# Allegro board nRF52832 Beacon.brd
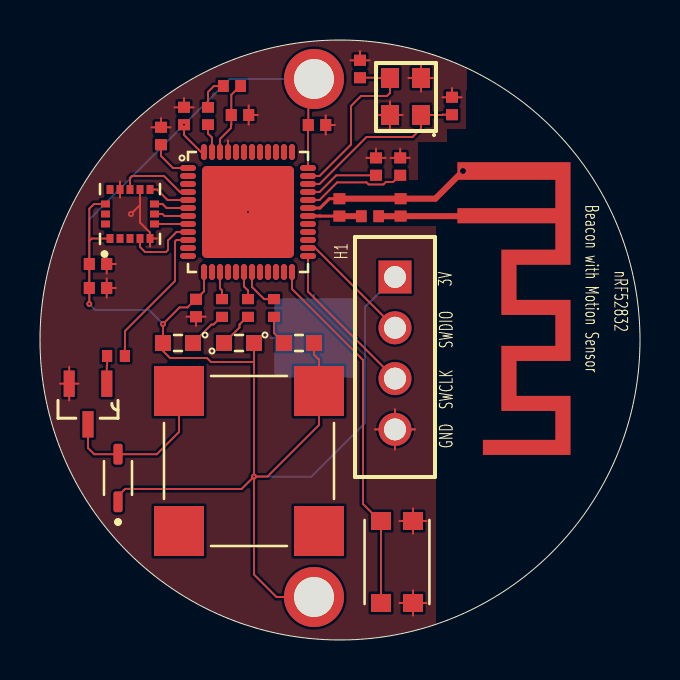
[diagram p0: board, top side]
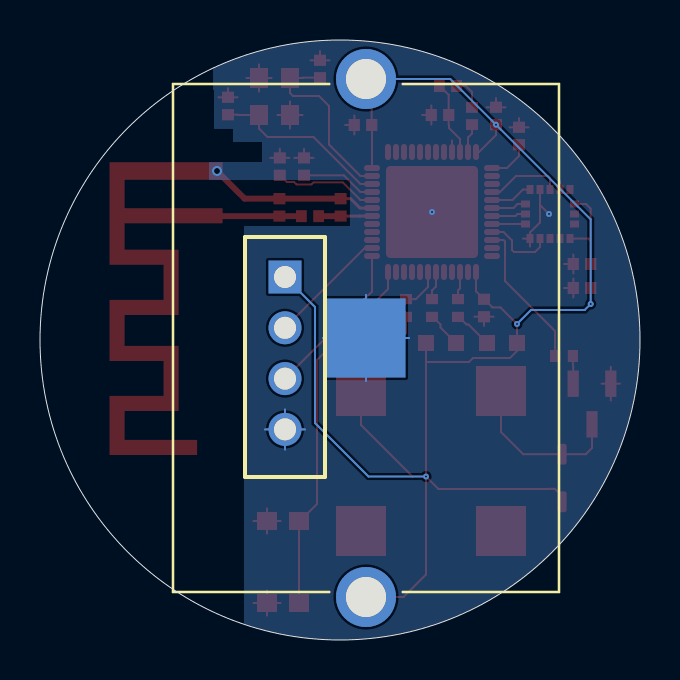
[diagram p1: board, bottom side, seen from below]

Outline 30 x 30 mm; copper layers: TOP, BOTTOM. Coordinates in mm from the lower left corner of the outline.
Outline path: circle c15,15 r15

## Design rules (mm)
constraint set DEFAULT: min track width 0.1

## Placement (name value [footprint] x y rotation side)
BT1  BK-5033  [BAT_BK-5033]  13.7 15.1 270 bottom
C1  100nF  [CAPC1005X55N]  7.8 16.6 270 top
C2  100nF  [CAPC1005X55N]  13.85 25.75 0 top
C3  4.7uF  [CAPC1005X55N]  7.2 26.2 90 top
C4  100nF  [CAPC1005X55N]  6.05 25.2 90 top
C5  DNP  [CAPC1005X55N]  18.01 23.67 90 top
C6  12pF  [CAPC1005X55N]  20.6 26.7 90 top
C7  100pF  [CAPC1005X55N]  16.8 23.67 90 top
C8  1uF  [CAPC1005X55N]  10 26.25 0 top
C9  12pF  [CAPC1005X55N]  16 28.55 90 top
C10  0.8pF  [CAPC1005X55N]  14.97 21.63 90 top
C11  NC  [CAPC1005X55N]  18.03 21.63 90 top
C12  100nF  [CAPC1005X55N]  2.9 17.6 0 top
C13  10uF  [CAPC1005X55N]  2.9 18.8 0 top
D1  LEDSMD_0603  [LEDM1608X80]  12.95 14.85 0 top
D2  LEDSMD_0603  [LEDM1608X80]  6.9 14.85 180 top
D3  LEDSMD_0603  [LEDM1608X80]  9.95 14.85 0 top
D4  S4  [SOD2513X120N]  3.9 8.1 90 top
H1  Header-4P  [4P_HEADER]  17.75 18.15 270 top
L1  10uH  [INDC1005X55N]  8.4 26.2 90 top
L2  15nH  [INDC1005X55N]  9.6 27.7 0 top
L3  3.9nH  [INDC1005X55N]  16.5 21.19 0 top
LS1  CMT-9504-87-SMT-TR  [XDCR_CMT-9504-87-SMT-TR]  10.45 8.95 270 top
R1  1kohm  [RESC1005X40N]  11.7 16.6 270 top
R2  1kohm  [RESC1005X40N]  9.1 16.6 270 top
R3  1kohm  [RESC1005X40N]  10.4 16.6 270 top
R4  220 ohms  [RESC1005X40N]  3.8 14.2 180 top
S1  KMR621NGLFS  [SW_KMR621NGLFS]  17.85 3.9 90 top
U1  NRF52832-QFAA-R  [QFN40P600X600X90-49N]  10.4 21.4 0 top
U2  LIS3DHTR  [XDCR_LIS3DHTR]  4.5 21.3 90 top
U3  BSS138K  [SOT95P240X110-3N]  2.4 11.8 270 top
Y1  32 MHz  [16MHZ_CRYSTAL_4PIN]  19.5 25.75 90 top

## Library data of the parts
BT1 = Coin Cell-CR2450-BK-5033
C1-C13 = Capacitor 0402
D1-D3 = LEDSMD_0603
D4 = Diode Schottky 0805 S4
H1 = Header-4P
L1-L3 = Inductor 0402
LS1 = Buzzer SMD 8.5x8.5x4
R1-R4 = Resistor 0402
S1 = Reset_Switch_Smd_KMR621NGLFS
U1 = NRF52832-QFAA-R
U2 = LIS3DHTR
U3 = BSS138K
Y1 = Crystal Oscillator 32 MHz

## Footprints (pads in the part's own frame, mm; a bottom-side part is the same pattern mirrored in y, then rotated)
4P_HEADER
  rect 1.65x1.65 hole 1.1: 1(0,0)
  round 1.65 hole 1.1: 2(2.54,0) 3(5.08,0) 4(7.62,0)
16MHZ_CRYSTAL_4PIN
  rect 1x0.9 smd: 1(0.5,0.45) 2(2.35,0.45) 3(2.35,2) 4(0.5,2)
BAT_BK-5033
  rect 3.96x3.96 smd: -(0,0)
  round 3 hole 2: S+1(-12.95,0) S+2(12.95,0)
CAPC1005X55N
  rect 0.56x0.6 smd: 1(-0.435,0) 2(0.435,0)
INDC1005X55N
  rect 0.54x0.6 smd: 1(-0.432,0) 2(0.432,0)
LEDM1608X80
  rect 0.8x0.8 smd: A(0.75,0) C(-0.75,0)
QFN40P600X600X90-49N
  custom 0.075x0.075 smd: 1(-3,2.2) 2(-3,1.8) 3(-3,1.4) 4(-3,1) 5(-3,0.6) 6(-3,0.2) 7(-3,-0.2) 8(-3,-0.6) 9(-3,-1) 10(-3,-1.4) 11(-3,-1.8) 12(-3,-2.2) 13(-2.2,-3) 14(-1.8,-3) 15(-1.4,-3) 16(-1,-3) 17(-0.6,-3) 18(-0.2,-3) 19(0.2,-3) 20(0.6,-3) 21(1,-3) 22(1.4,-3) 23(1.8,-3) 24(2.2,-3) 25(3,-2.2) 26(3,-1.8) 27(3,-1.4) 28(3,-1) 29(3,-0.6) 30(3,-0.2) 31(3,0.2) 32(3,0.6) 33(3,1) 34(3,1.4) 35(3,1.8) 36(3,2.2) 37(2.2,3) 38(1.8,3) 39(1.4,3) 40(1,3) 41(0.6,3) 42(0.2,3) 43(-0.2,3) 44(-0.6,3) 45(-1,3) 46(-1.4,3) 47(-1.8,3) 48(-2.2,3)
  custom 1.15x1.15 smd: 49(0,0)
RESC1005X40N
  rect 0.51x0.6 smd: 1(-0.445,0) 2(0.445,0)
SOD2513X120N
  custom 0.115x0.115 smd: A(1.19,0) C(-1.19,0)
SOT95P240X110-3N
  rect 1.321x0.559 smd: 1(-1.016,0.94) 2(-1.016,-0.94) 3(1.016,0)
SW_KMR621NGLFS
  rect 0.9x1 smd: 1_1(-2.05,0.8) 1_2(2.05,0.8) 2_1(-2.05,-0.8) 2_2(2.05,-0.8)
XDCR_CMT-9504-87-SMT-TR
  rect 2.5x2.5 smd: 1(3.5,3.5) 2(3.5,-3.5) N(-3.5,-3.5) P(-3.5,3.5)
XDCR_LIS3DHTR
  rect 0.45x0.35 smd: 1(-1.225,1) 2(-1.225,0.5) 3(-1.225,0) 4(-1.225,-0.5) 5(-1.225,-1) 9(1.225,-1) 10(1.225,-0.5) 11(1.225,0) 12(1.225,0.5) 13(1.225,1)
  rect 0.35x0.45 smd: 6(-0.5,-1.225) 7(0,-1.225) 8(0.5,-1.225) 14(0.5,1.225) 15(0,1.225) 16(-0.5,1.225)

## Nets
GND: BT1.- C1.2 C2.2 C3.2 C4.2 C5.2 C6.2 C7.2 C8.2 C9.2 C10.2 C11.2 C12.2 C13.2 H1.4 S1.2_1 S1.2_2(2__1) U1.31 U1.45 U1.49 U2.5 U2.10 U2.12 U3.2(S) Y1.2 Y1.4
VDD_NRF: BT1.S+1 BT1.S+2 C1.1 C2.1 C3.1 C12.1 C13.1 D1.A D2.A D3.A D4.C H1.1 LS1.P U1.13 U1.36 U1.48 U2.1(VDD_IO) U2.14
CS: U1.6 U2.8
INT1: U1.4 U2.11
INT2: U1.5 U2.9
P0_08: R4.1 U1.10
P0_09/NFC1: U1.11
P0_10/NFC2: U1.12
P0_12: R2.1 U1.15
P0_15: R3.1 U1.18
P0_16: R1.1 U1.19
P0_21: S1.1_1 S1.1_2 U1.24
SD0: U1.7 U2.7
SDI: U1.8 U2.6
SPC: U1.9 U2.4
SWDCLK: H1.3 U1.25
SWDIO: H1.2 U1.26
XC1: C6.1 U1.34 Y1.1
XC2: C9.1 U1.35(XC2) Y1.3(XC2)
N01519: C10.1 L3.1 U1.30
N09596: C4.1 U1.1
N09735: C5.1 U1.32
N10563: C7.1 U1.33
N12077: D4.A LS1.N U3.3
N14036: L1.1 U1.47
N14480: C8.1 L2.2 U1.46
N17584: L1.2 L2.1
N168151: D1.C R1.2
N168591: D2.C R2.2
N169031: D3.C R3.2
N709599: R4.2 U3.1
N7081621: C11.1 L3.2

Pads without a net: LS1 1 2; U1 2 3 14 16 17 20 21 22 23 27 28 29 37 38 39 40 41 42 43 44; U2 2 3 13 15 16

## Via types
v1: diameter 0.3, hole 0.1, TOP to BOTTOM, 7 vias
v2: diameter 0.5, hole 0.3, TOP to BOTTOM, 1 via

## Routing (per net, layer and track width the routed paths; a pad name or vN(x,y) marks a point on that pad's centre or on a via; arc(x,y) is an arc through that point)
GND: length 59.2
  TOP w0.1: C13.2 3.34,19.28 ; C13.2 3.34,18.32 ; C13.2 3.79,18.8 ; Y1.2 19.05,28.78 ; Y1.2 18.42,28.1 ; Y1.2 19.68,28.1 ; Y1.2 19.05,27.42 ; 5.57,25.63 C4.2 ; C4.2 6.05,26.09 ; C4.2 6.53,25.63 ; S1.2_2 19.33,5.95 ; S1.2_2 17.97,5.95 ; S1.2_2 18.65,6.58 ; S1.2_2 18.65,5.32 ; 5,21.75 5,20.87 5.5,20.37 5.5,20.07 ; 5,21.75 v1(4.55,21.3) ; 5,21.75 U2.10 ; 16.87,26.25 Y1.4 ; Y1.4 18.13,26.25 ; Y1.4 17.5,25.57 ; Y1.4 17.5,26.93 ; 15.52,28.98 16,28.98 ; 16,28.98 16,29.44 ; 16,28.98 16.48,28.98 ; 7.32,16.16 C1.2 ; C1.2 7.8,15.71 ; C1.2 8.28,16.16 ; 1.46,11.98 U3.2 ; U3.2 1.92,12.82 ; U3.2 1,12.82 ; U3.2 1.46,13.65 ; 3.34,17.12 C12.2 ; C12.2 3.34,18.08 ; C12.2 3.79,17.6 ; H1.4 17.75,11.53 ; H1.4 17.75,9.53 ; H1.4 16.75,10.53 ; H1.4 18.75,10.53 ; 18.65,1.22 S1.2_1 ; S1.2_1 18.65,2.48 ; S1.2_1 19.33,1.85 ; S1.2_1 17.97,1.85 ; 14.29,25.75 14.29,26.23 ; 14.29,25.75 14.29,25.27 ; 14.29,25.75 14.74,25.75 ; 17.53,24.11 C5.2 ; C5.2 18.01,24.56 ; C5.2 18.49,24.11 ; 5.5,19.67 5.5,20.07 ; 5.5,20.07 5.85,20.07 ; 20.12,27.13 C6.2 ; C6.2 21.08,27.13 ; C6.2 20.6,27.59 ; C7.2 16.8,24.56 ; C7.2 16.32,24.11 ; C7.2 17.28,24.11 ; C8.2 10.89,26.25 ; C8.2 10.43,26.73 ; C8.2 10.43,25.77 ; C3.2 7.68,26.63 ; C3.2 6.72,26.63 ; C3.2 7.2,27.09 ; 4,22.12 U2.12 4,22.93 ; 9.4,24.98 U1.45
  TOP w0.15: C10.2 14.47,22.07 14,21.6 U1.31
  TOP w0.3: v2(21.15,23.45) 19.77,22.07 C11.2 C10.2
  BOTTOM w0.1: 11.54,15.1 BT1.- ; BT1.- 13.7,12.94 ; BT1.- 15.86,15.1 ; BT1.- 13.7,17.26 ; 17.75,9.53 H1.4 ; H1.4 17.75,11.53 ; H1.4 16.75,10.53 ; H1.4 18.75,10.53
  vias: v1(10.4,21.4)
VDD_NRF: length 91.1
  TOP w0.1: U2.14 2.7,21.8 2.46,21.57 2.46,19.95 ; D4.C 3.9,7.2 4.26,7.56 4.53,7.56 4.54,7.55 10.08,7.55 v1(10.7,8.17) ; BT1.S+1 13.7,27.2 13.41,26.91 C2.1 13.4,25.73 U1.36 ; 2.46,19.95 2.59,20.07 3.5,20.07 ; 2.46,19.95 C13.1 C12.1 v1(2.46,16.8) ; U1.13 8.2,17.43 C1.1 7.78,17.04 7.37,16.63 6.98,16.63 v1(6.15,15.8) D2.A 6.15,14.45 6.5,14.1 8.35,14.1 8.55,13.9 10.7,13.9 ; 10.7,13.9 v1(10.7,8.17) ; 10.7,13.9 D3.A ; v1(10.7,8.17) 11.37,8.17 13.95,10.75 LS1.P 13.95,14.02 13.7,14.27 D1.A ; v1(10.7,8.17) 10.7,3.27 11.82,2.15 BT1.S+2 ; v1(7.2,25.77) 7.2,25.25 8.05,24.4 U1.48
  BOTTOM w0.1: BT1.S+1 9.48,28.05 v1(7.2,25.77) 2.46,21.03 v1(2.46,16.8) 2.77,16.5 5.45,16.5 v1(6.15,15.8) ; H1.1 16.25,16.65 16.25,10.85 13.57,8.17 v1(10.7,8.17)
CS: length 1.8
  TOP w0.1: U1.6 6.33,21.6 6.13,21.8 U2.8
INT1: length 3.8
  TOP w0.1: U1.4 7,22.4 6.2,23.2 4.6,23.2 4.5,23.1 U2.11
INT2: length 2.1
  TOP w0.1: U1.5 6.38,22 5.85,22.52 U2.9
P0_08: length 7.4
  TOP w0.1: U1.10 6.82,20 6.75,19.93 6.75,17.95 4.25,15.45 4.25,14.68 4.24,14.68 4.24,14.2
P0_12: length 1.4
  TOP w0.1: R2.1 9.1,17.48 9,17.58 U1.15
P0_15: length 1.4
  TOP w0.1: U1.18 10.2,17.68 10.4,17.48 R3.1
P0_16: length 2.1
  TOP w0.1: U1.19 10.6,17.65 11.21,17.05 R1.1
P0_21: length 18.4
  TOP w0.1: U1.24 12.6,17.55 16.15,14 16.15,6.8 17,5.95 S1.1_2 S1.1_1
SD0: length 1.7
  TOP w0.1: U2.7 6.13,21.3 6.23,21.2 U1.7
SDI: length 1.7
  TOP w0.1: U2.6 U1.8
SPC: length 3.6
  TOP w0.1: 5,20.07 5,19.65 5.25,19.4 6.3,19.4 6.4,19.5 6.4,19.98 6.82,20.4 U1.9
SWDCLK: length 7.9
  TOP w0.1: H1.3 13.4,17.42 U1.25
SWDIO: length 6
  TOP w0.1: U1.26 13.76,19.6 H1.2
XC1: length 9
  TOP w0.1: U1.34 13.98,22.8 16.33,25.15 18.63,25.15 19.05,25.57 Y1.1 20.11,26.25 20.12,26.27 C6.1
XC2: length 9.2
  TOP w0.1: U1.35 13.98,23.2 15.55,24.77 15.55,26.7 16.05,27.2 17.35,27.2 17.5,27.35 Y1.3 16.87,28.1 16.86,28.12 C9.1
N01519: length 2.7
  TOP w0.15: C10.1 14.01,21.2 14,21.2 U1.30
  TOP w0.3: C10.1 16.06,21.2 L3.1
N09596: length 2.2
  TOP w0.1: U1.1 6.65,23.6 6.05,24.2 C4.1
N09735: length 5.2
  TOP w0.1: U1.32 13.98,22 14.86,22.88 16.32,22.88 16.43,22.78 17.17,22.78 17.3,22.9 17.66,22.9 17.99,23.23 C5.1
N10563: length 3.7
  TOP w0.1: U1.33 13.98,22.4 14.81,23.23 C7.1
N12077: length 8.4
  TOP w0.1: LS1.N 6.95,10.4 5.84,9.29 D4.A 2.71,9.29 2.4,9.6 U3.3
N14036: length 1.5
  TOP w0.1: U1.47 8.6,25.12 8.4,25.32 L1.1
N14480: length 3.7
  TOP w0.1: L2.2 10.01,27.7 9.57,27.26 C8.1 9.57,25.77 9.55,25.76 9.55,25.6 9,25.05 U1.46
N17584: length 1.7
  TOP w0.1: L1.2 8.4,27.4 8.7,27.7 L2.1
N168151: length 1.5
  TOP w0.1: R1.2 11.7,15.35 D1.C
N168591: length 2
  TOP w0.1: R2.2 9.05,16.16 8.67,15.77 8.57,15.77 D2.C
N169031: length 1.8
  TOP w0.1: R3.2 10.36,16.16 9.97,15.77 9.97,15.62 D3.C
N709599: length 1.4
  TOP w0.1: U3.1 3.34,13.71 3.36,13.72 R4.2
N7081621: length 4.3
  TOP w0.3: 21.2,21.2 C11.1 18.02,21.19 L3.2

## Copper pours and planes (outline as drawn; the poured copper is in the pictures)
GND on TOP: 21.35,28.59 0.02,15.83 19.8,0.79 19.8,0.79 19.8,20.7 14.5,20.7 14.5,23 18.9,23 18.9,24.9 20.35,24.9 20.35,25.55 21.3,25.55 21.3,27.5 21.35,27.5
GND on BOTTOM: 21.35,28.59 0.02,15.83 19.8,0.79 19.8,0.79 19.8,20.7 14.5,20.7 14.5,23 21.55,23 21.55,23.9 18.9,23.9 18.9,24.9 20.35,24.9 20.35,25.56 21.3,25.56 21.3,27.5 21.35,27.5
Net_7 on TOP (solid shape): 26.52,18.76 23.82,18.76 23.82,17.01 26.52,17.01 26.52,13.95 23.82,13.95 23.82,12.21 26.52,12.21 26.52,9.25 22.14,9.25 22.14,10.01 25.77,10.01 25.77,11.45 23.07,11.45 23.07,14.71 25.77,14.71 25.77,16.25 23.07,16.25 23.07,19.52 25.77,19.52 25.77,20.84 20.87,20.84 20.87,21.59 25.77,21.59 25.77,23.01 20.87,23.01 20.87,23.89 26.52,23.89

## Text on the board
Ref Des/Silkscreen Top: 3V | SWDIO | SWCLK | GND | Beacon with Motion Sensor | nRF52832
